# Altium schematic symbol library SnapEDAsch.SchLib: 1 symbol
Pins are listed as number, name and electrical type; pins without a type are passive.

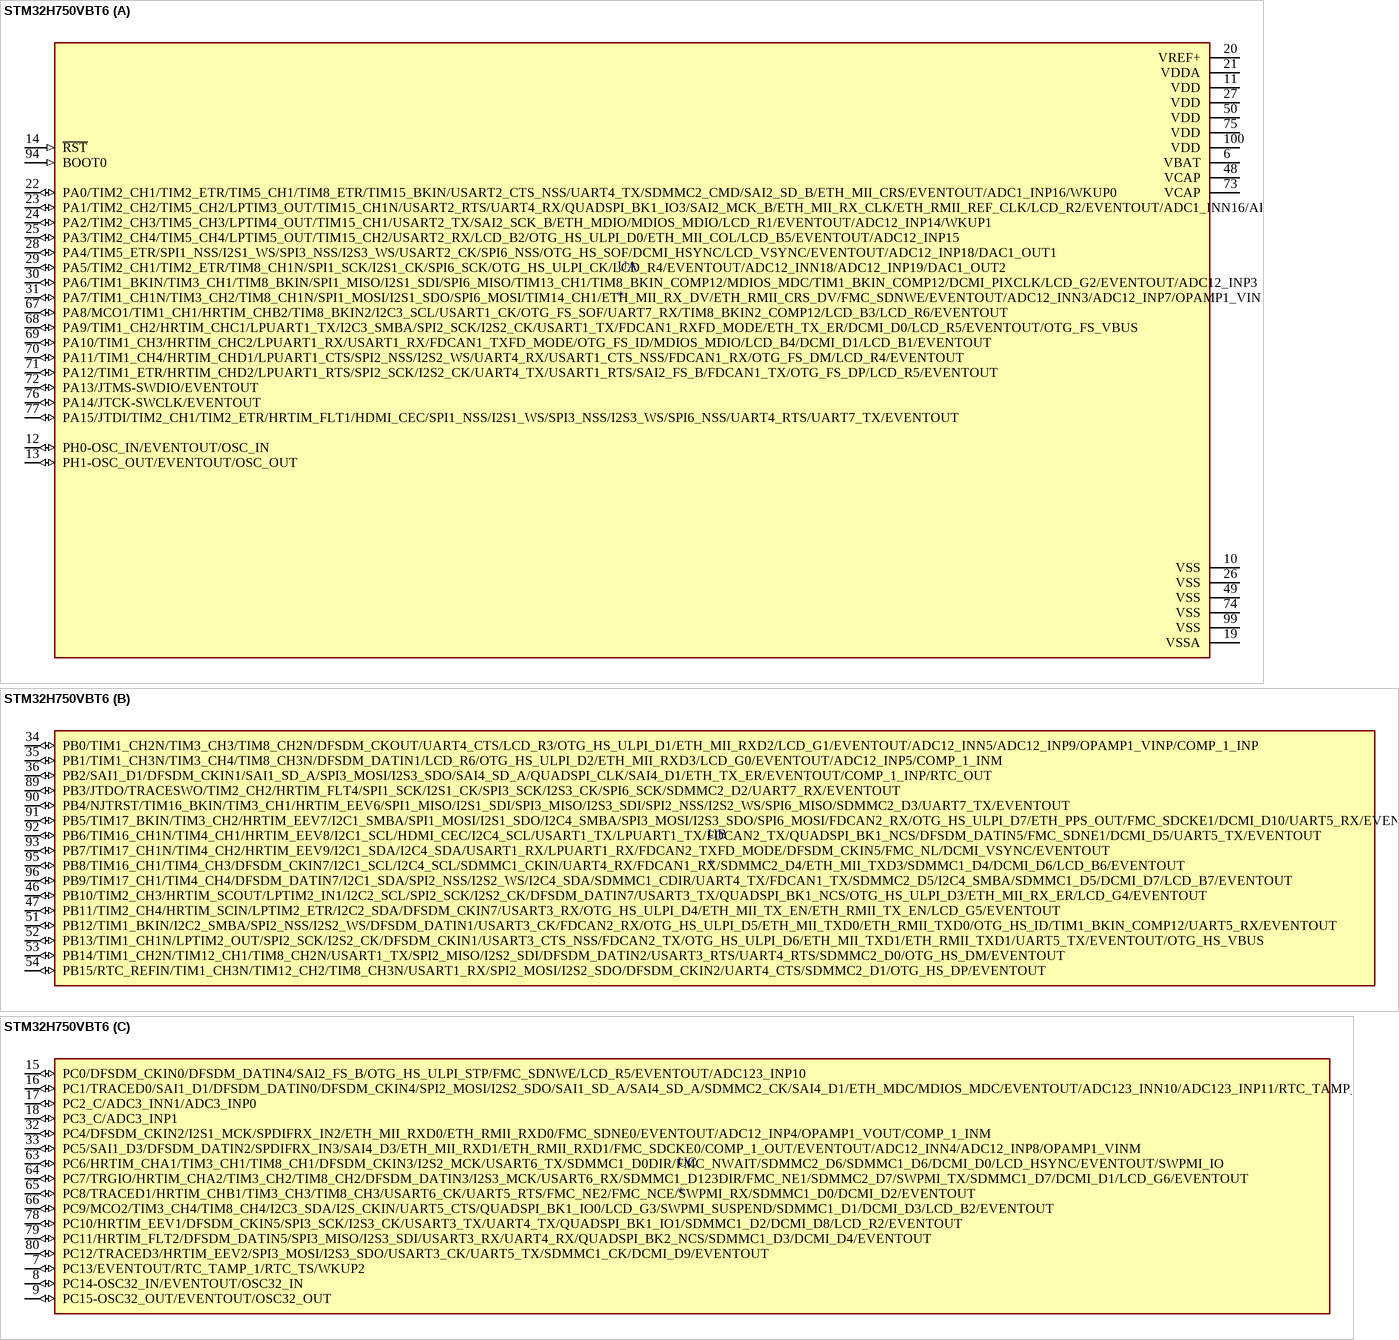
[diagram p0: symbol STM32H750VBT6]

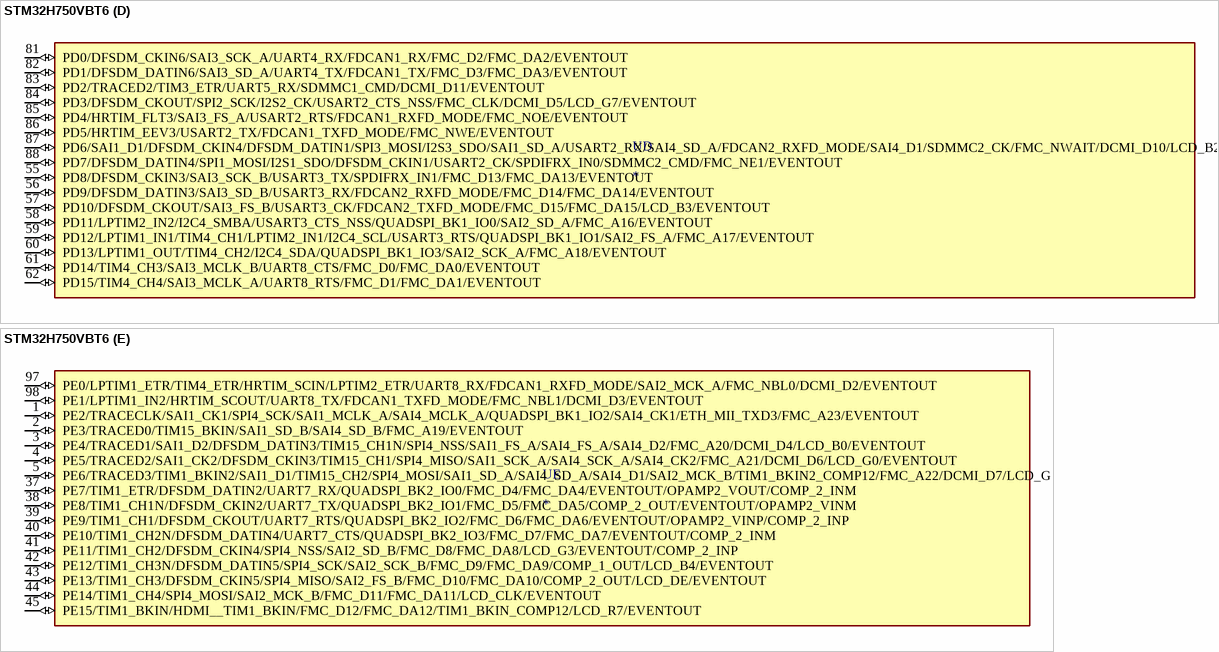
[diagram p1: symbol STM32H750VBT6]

## STM32H750VBT6
designator U
ARMÂ® CortexÂ®-M7 STM32H7 Microcontroller IC 32-Bit 480MHz 128KB _128K x 8_ FLASH 100-LQFP _14x14_; MF: STMicroelectronics; MP: STM32H750VBT6
footprint QFP50P1600X1600X160-100N
part A pins: 6 VBAT (power), 10 VSS (power), 11 VDD (power), 12 PH0-OSC_IN/EVENTOUT/OSC_IN (io), 13 PH1-OSC_OUT/EVENTOUT/OSC_OUT (io), 14 ~{RST} (in), 19 VSSA (power), 20 VREF+ (power), 21 VDDA (power), 22 PA0/TIM2_CH1/TIM2_ETR/TIM5_CH1/TIM8_ETR/TIM15_BKIN/USART2_CTS_NSS/UART4_TX/SDMMC2_CMD/SAI2_SD_B/ETH_MII_CRS/EVENTOUT/ADC1_INP16/WKUP0 (io), 23 PA1/TIM2_CH2/TIM5_CH2/LPTIM3_OUT/TIM15_CH1N/USART2_RTS/UART4_RX/QUADSPI_BK1_IO3/SAI2_MCK_B/ETH_MII_RX_CLK/ETH_RMII_REF_CLK/LCD_R2/EVENTOUT/ADC1_INN16/ADC1_INP17 (io), 24 PA2/TIM2_CH3/TIM5_CH3/LPTIM4_OUT/TIM15_CH1/USART2_TX/SAI2_SCK_B/ETH_MDIO/MDIOS_MDIO/LCD_R1/EVENTOUT/ADC12_INP14/WKUP1 (io), 25 PA3/TIM2_CH4/TIM5_CH4/LPTIM5_OUT/TIM15_CH2/USART2_RX/LCD_B2/OTG_HS_ULPI_D0/ETH_MII_COL/LCD_B5/EVENTOUT/ADC12_INP15 (io), 26 VSS (power), 27 VDD (power), 28 PA4/TIM5_ETR/SPI1_NSS/I2S1_WS/SPI3_NSS/I2S3_WS/USART2_CK/SPI6_NSS/OTG_HS_SOF/DCMI_HSYNC/LCD_VSYNC/EVENTOUT/ADC12_INP18/DAC1_OUT1 (io), 29 PA5/TIM2_CH1/TIM2_ETR/TIM8_CH1N/SPI1_SCK/I2S1_CK/SPI6_SCK/OTG_HS_ULPI_CK/LCD_R4/EVENTOUT/ADC12_INN18/ADC12_INP19/DAC1_OUT2 (io), 30 PA6/TIM1_BKIN/TIM3_CH1/TIM8_BKIN/SPI1_MISO/I2S1_SDI/SPI6_MISO/TIM13_CH1/TIM8_BKIN_COMP12/MDIOS_MDC/TIM1_BKIN_COMP12/DCMI_PIXCLK/LCD_G2/EVENTOUT/ADC12_INP3 (io), 31 PA7/TIM1_CH1N/TIM3_CH2/TIM8_CH1N/SPI1_MOSI/I2S1_SDO/SPI6_MOSI/TIM14_CH1/ETH_MII_RX_DV/ETH_RMII_CRS_DV/FMC_SDNWE/EVENTOUT/ADC12_INN3/ADC12_INP7/OPAMP1_VINM (io), 48 VCAP (power), 49 VSS (power), 50 VDD (power), 67 PA8/MCO1/TIM1_CH1/HRTIM_CHB2/TIM8_BKIN2/I2C3_SCL/USART1_CK/OTG_FS_SOF/UART7_RX/TIM8_BKIN2_COMP12/LCD_B3/LCD_R6/EVENTOUT (io), 68 PA9/TIM1_CH2/HRTIM_CHC1/LPUART1_TX/I2C3_SMBA/SPI2_SCK/I2S2_CK/USART1_TX/FDCAN1_RXFD_MODE/ETH_TX_ER/DCMI_D0/LCD_R5/EVENTOUT/OTG_FS_VBUS (io), 69 PA10/TIM1_CH3/HRTIM_CHC2/LPUART1_RX/USART1_RX/FDCAN1_TXFD_MODE/OTG_FS_ID/MDIOS_MDIO/LCD_B4/DCMI_D1/LCD_B1/EVENTOUT (io), 70 PA11/TIM1_CH4/HRTIM_CHD1/LPUART1_CTS/SPI2_NSS/I2S2_WS/UART4_RX/USART1_CTS_NSS/FDCAN1_RX/OTG_FS_DM/LCD_R4/EVENTOUT (io), 71 PA12/TIM1_ETR/HRTIM_CHD2/LPUART1_RTS/SPI2_SCK/I2S2_CK/UART4_TX/USART1_RTS/SAI2_FS_B/FDCAN1_TX/OTG_FS_DP/LCD_R5/EVENTOUT (io), 72 PA13/JTMS-SWDIO/EVENTOUT (io), 73 VCAP (power), 74 VSS (power), 75 VDD (power), 76 PA14/JTCK-SWCLK/EVENTOUT (io), 77 PA15/JTDI/TIM2_CH1/TIM2_ETR/HRTIM_FLT1/HDMI_CEC/SPI1_NSS/I2S1_WS/SPI3_NSS/I2S3_WS/SPI6_NSS/UART4_RTS/UART7_TX/EVENTOUT (io), 94 BOOT0 (in), 99 VSS (power), 100 VDD (power)
part B pins: 34 PB0/TIM1_CH2N/TIM3_CH3/TIM8_CH2N/DFSDM_CKOUT/UART4_CTS/LCD_R3/OTG_HS_ULPI_D1/ETH_MII_RXD2/LCD_G1/EVENTOUT/ADC12_INN5/ADC12_INP9/OPAMP1_VINP/COMP_1_INP (io), 35 PB1/TIM1_CH3N/TIM3_CH4/TIM8_CH3N/DFSDM_DATIN1/LCD_R6/OTG_HS_ULPI_D2/ETH_MII_RXD3/LCD_G0/EVENTOUT/ADC12_INP5/COMP_1_INM (io), 36 PB2/SAI1_D1/DFSDM_CKIN1/SAI1_SD_A/SPI3_MOSI/I2S3_SDO/SAI4_SD_A/QUADSPI_CLK/SAI4_D1/ETH_TX_ER/EVENTOUT/COMP_1_INP/RTC_OUT (io), 46 PB10/TIM2_CH3/HRTIM_SCOUT/LPTIM2_IN1/I2C2_SCL/SPI2_SCK/I2S2_CK/DFSDM_DATIN7/USART3_TX/QUADSPI_BK1_NCS/OTG_HS_ULPI_D3/ETH_MII_RX_ER/LCD_G4/EVENTOUT (io), 47 PB11/TIM2_CH4/HRTIM_SCIN/LPTIM2_ETR/I2C2_SDA/DFSDM_CKIN7/USART3_RX/OTG_HS_ULPI_D4/ETH_MII_TX_EN/ETH_RMII_TX_EN/LCD_G5/EVENTOUT (io), 51 PB12/TIM1_BKIN/I2C2_SMBA/SPI2_NSS/I2S2_WS/DFSDM_DATIN1/USART3_CK/FDCAN2_RX/OTG_HS_ULPI_D5/ETH_MII_TXD0/ETH_RMII_TXD0/OTG_HS_ID/TIM1_BKIN_COMP12/UART5_RX/EVENTOUT (io), 52 PB13/TIM1_CH1N/LPTIM2_OUT/SPI2_SCK/I2S2_CK/DFSDM_CKIN1/USART3_CTS_NSS/FDCAN2_TX/OTG_HS_ULPI_D6/ETH_MII_TXD1/ETH_RMII_TXD1/UART5_TX/EVENTOUT/OTG_HS_VBUS (io), 53 PB14/TIM1_CH2N/TIM12_CH1/TIM8_CH2N/USART1_TX/SPI2_MISO/I2S2_SDI/DFSDM_DATIN2/USART3_RTS/UART4_RTS/SDMMC2_D0/OTG_HS_DM/EVENTOUT (io), 54 PB15/RTC_REFIN/TIM1_CH3N/TIM12_CH2/TIM8_CH3N/USART1_RX/SPI2_MOSI/I2S2_SDO/DFSDM_CKIN2/UART4_CTS/SDMMC2_D1/OTG_HS_DP/EVENTOUT (io), 89 PB3/JTDO/TRACESWO/TIM2_CH2/HRTIM_FLT4/SPI1_SCK/I2S1_CK/SPI3_SCK/I2S3_CK/SPI6_SCK/SDMMC2_D2/UART7_RX/EVENTOUT (io), 90 PB4/NJTRST/TIM16_BKIN/TIM3_CH1/HRTIM_EEV6/SPI1_MISO/I2S1_SDI/SPI3_MISO/I2S3_SDI/SPI2_NSS/I2S2_WS/SPI6_MISO/SDMMC2_D3/UART7_TX/EVENTOUT (io), 91 PB5/TIM17_BKIN/TIM3_CH2/HRTIM_EEV7/I2C1_SMBA/SPI1_MOSI/I2S1_SDO/I2C4_SMBA/SPI3_MOSI/I2S3_SDO/SPI6_MOSI/FDCAN2_RX/OTG_HS_ULPI_D7/ETH_PPS_OUT/FMC_SDCKE1/DCMI_D10/UART5_RX/EVENTOUT (io), 92 PB6/TIM16_CH1N/TIM4_CH1/HRTIM_EEV8/I2C1_SCL/HDMI_CEC/I2C4_SCL/USART1_TX/LPUART1_TX/FDCAN2_TX/QUADSPI_BK1_NCS/DFSDM_DATIN5/FMC_SDNE1/DCMI_D5/UART5_TX/EVENTOUT (io), 93 PB7/TIM17_CH1N/TIM4_CH2/HRTIM_EEV9/I2C1_SDA/I2C4_SDA/USART1_RX/LPUART1_RX/FDCAN2_TXFD_MODE/DFSDM_CKIN5/FMC_NL/DCMI_VSYNC/EVENTOUT (io), 95 PB8/TIM16_CH1/TIM4_CH3/DFSDM_CKIN7/I2C1_SCL/I2C4_SCL/SDMMC1_CKIN/UART4_RX/FDCAN1_RX/SDMMC2_D4/ETH_MII_TXD3/SDMMC1_D4/DCMI_D6/LCD_B6/EVENTOUT (io), 96 PB9/TIM17_CH1/TIM4_CH4/DFSDM_DATIN7/I2C1_SDA/SPI2_NSS/I2S2_WS/I2C4_SDA/SDMMC1_CDIR/UART4_TX/FDCAN1_TX/SDMMC2_D5/I2C4_SMBA/SDMMC1_D5/DCMI_D7/LCD_B7/EVENTOUT (io)
part C pins: 7 PC13/EVENTOUT/RTC_TAMP_1/RTC_TS/WKUP2 (io), 8 PC14-OSC32_IN/EVENTOUT/OSC32_IN (io), 9 PC15-OSC32_OUT/EVENTOUT/OSC32_OUT (io), 15 PC0/DFSDM_CKIN0/DFSDM_DATIN4/SAI2_FS_B/OTG_HS_ULPI_STP/FMC_SDNWE/LCD_R5/EVENTOUT/ADC123_INP10 (io), 16 PC1/TRACED0/SAI1_D1/DFSDM_DATIN0/DFSDM_CKIN4/SPI2_MOSI/I2S2_SDO/SAI1_SD_A/SAI4_SD_A/SDMMC2_CK/SAI4_D1/ETH_MDC/MDIOS_MDC/EVENTOUT/ADC123_INN10/ADC123_INP11/RTC_TAMP_3/WKUP5 (io), 17 PC2_C/ADC3_INN1/ADC3_INP0 (io), 18 PC3_C/ADC3_INP1 (io), 32 PC4/DFSDM_CKIN2/I2S1_MCK/SPDIFRX_IN2/ETH_MII_RXD0/ETH_RMII_RXD0/FMC_SDNE0/EVENTOUT/ADC12_INP4/OPAMP1_VOUT/COMP_1_INM (io), 33 PC5/SAI1_D3/DFSDM_DATIN2/SPDIFRX_IN3/SAI4_D3/ETH_MII_RXD1/ETH_RMII_RXD1/FMC_SDCKE0/COMP_1_OUT/EVENTOUT/ADC12_INN4/ADC12_INP8/OPAMP1_VINM (io), 63 PC6/HRTIM_CHA1/TIM3_CH1/TIM8_CH1/DFSDM_CKIN3/I2S2_MCK/USART6_TX/SDMMC1_D0DIR/FMC_NWAIT/SDMMC2_D6/SDMMC1_D6/DCMI_D0/LCD_HSYNC/EVENTOUT/SWPMI_IO (io), 64 PC7/TRGIO/HRTIM_CHA2/TIM3_CH2/TIM8_CH2/DFSDM_DATIN3/I2S3_MCK/USART6_RX/SDMMC1_D123DIR/FMC_NE1/SDMMC2_D7/SWPMI_TX/SDMMC1_D7/DCMI_D1/LCD_G6/EVENTOUT (io), 65 PC8/TRACED1/HRTIM_CHB1/TIM3_CH3/TIM8_CH3/USART6_CK/UART5_RTS/FMC_NE2/FMC_NCE/SWPMI_RX/SDMMC1_D0/DCMI_D2/EVENTOUT (io), 66 PC9/MCO2/TIM3_CH4/TIM8_CH4/I2C3_SDA/I2S_CKIN/UART5_CTS/QUADSPI_BK1_IO0/LCD_G3/SWPMI_SUSPEND/SDMMC1_D1/DCMI_D3/LCD_B2/EVENTOUT (io), 78 PC10/HRTIM_EEV1/DFSDM_CKIN5/SPI3_SCK/I2S3_CK/USART3_TX/UART4_TX/QUADSPI_BK1_IO1/SDMMC1_D2/DCMI_D8/LCD_R2/EVENTOUT (io), 79 PC11/HRTIM_FLT2/DFSDM_DATIN5/SPI3_MISO/I2S3_SDI/USART3_RX/UART4_RX/QUADSPI_BK2_NCS/SDMMC1_D3/DCMI_D4/EVENTOUT (io), 80 PC12/TRACED3/HRTIM_EEV2/SPI3_MOSI/I2S3_SDO/USART3_CK/UART5_TX/SDMMC1_CK/DCMI_D9/EVENTOUT (io)
part D pins: 55 PD8/DFSDM_CKIN3/SAI3_SCK_B/USART3_TX/SPDIFRX_IN1/FMC_D13/FMC_DA13/EVENTOUT (io), 56 PD9/DFSDM_DATIN3/SAI3_SD_B/USART3_RX/FDCAN2_RXFD_MODE/FMC_D14/FMC_DA14/EVENTOUT (io), 57 PD10/DFSDM_CKOUT/SAI3_FS_B/USART3_CK/FDCAN2_TXFD_MODE/FMC_D15/FMC_DA15/LCD_B3/EVENTOUT (io), 58 PD11/LPTIM2_IN2/I2C4_SMBA/USART3_CTS_NSS/QUADSPI_BK1_IO0/SAI2_SD_A/FMC_A16/EVENTOUT (io), 59 PD12/LPTIM1_IN1/TIM4_CH1/LPTIM2_IN1/I2C4_SCL/USART3_RTS/QUADSPI_BK1_IO1/SAI2_FS_A/FMC_A17/EVENTOUT (io), 60 PD13/LPTIM1_OUT/TIM4_CH2/I2C4_SDA/QUADSPI_BK1_IO3/SAI2_SCK_A/FMC_A18/EVENTOUT (io), 61 PD14/TIM4_CH3/SAI3_MCLK_B/UART8_CTS/FMC_D0/FMC_DA0/EVENTOUT (io), 62 PD15/TIM4_CH4/SAI3_MCLK_A/UART8_RTS/FMC_D1/FMC_DA1/EVENTOUT (io), 81 PD0/DFSDM_CKIN6/SAI3_SCK_A/UART4_RX/FDCAN1_RX/FMC_D2/FMC_DA2/EVENTOUT (io), 82 PD1/DFSDM_DATIN6/SAI3_SD_A/UART4_TX/FDCAN1_TX/FMC_D3/FMC_DA3/EVENTOUT (io), 83 PD2/TRACED2/TIM3_ETR/UART5_RX/SDMMC1_CMD/DCMI_D11/EVENTOUT (io), 84 PD3/DFSDM_CKOUT/SPI2_SCK/I2S2_CK/USART2_CTS_NSS/FMC_CLK/DCMI_D5/LCD_G7/EVENTOUT (io), 85 PD4/HRTIM_FLT3/SAI3_FS_A/USART2_RTS/FDCAN1_RXFD_MODE/FMC_NOE/EVENTOUT (io), 86 PD5/HRTIM_EEV3/USART2_TX/FDCAN1_TXFD_MODE/FMC_NWE/EVENTOUT (io), 87 PD6/SAI1_D1/DFSDM_CKIN4/DFSDM_DATIN1/SPI3_MOSI/I2S3_SDO/SAI1_SD_A/USART2_RX/SAI4_SD_A/FDCAN2_RXFD_MODE/SAI4_D1/SDMMC2_CK/FMC_NWAIT/DCMI_D10/LCD_B2/EVENTOUT (io), 88 PD7/DFSDM_DATIN4/SPI1_MOSI/I2S1_SDO/DFSDM_CKIN1/USART2_CK/SPDIFRX_IN0/SDMMC2_CMD/FMC_NE1/EVENTOUT (io)
part E pins: 1 PE2/TRACECLK/SAI1_CK1/SPI4_SCK/SAI1_MCLK_A/SAI4_MCLK_A/QUADSPI_BK1_IO2/SAI4_CK1/ETH_MII_TXD3/FMC_A23/EVENTOUT (io), 2 PE3/TRACED0/TIM15_BKIN/SAI1_SD_B/SAI4_SD_B/FMC_A19/EVENTOUT (io), 3 PE4/TRACED1/SAI1_D2/DFSDM_DATIN3/TIM15_CH1N/SPI4_NSS/SAI1_FS_A/SAI4_FS_A/SAI4_D2/FMC_A20/DCMI_D4/LCD_B0/EVENTOUT (io), 4 PE5/TRACED2/SAI1_CK2/DFSDM_CKIN3/TIM15_CH1/SPI4_MISO/SAI1_SCK_A/SAI4_SCK_A/SAI4_CK2/FMC_A21/DCMI_D6/LCD_G0/EVENTOUT (io), 5 PE6/TRACED3/TIM1_BKIN2/SAI1_D1/TIM15_CH2/SPI4_MOSI/SAI1_SD_A/SAI4_SD_A/SAI4_D1/SAI2_MCK_B/TIM1_BKIN2_COMP12/FMC_A22/DCMI_D7/LCD_G1/EVENTOUT (io), 37 PE7/TIM1_ETR/DFSDM_DATIN2/UART7_RX/QUADSPI_BK2_IO0/FMC_D4/FMC_DA4/EVENTOUT/OPAMP2_VOUT/COMP_2_INM (io), 38 PE8/TIM1_CH1N/DFSDM_CKIN2/UART7_TX/QUADSPI_BK2_IO1/FMC_D5/FMC_DA5/COMP_2_OUT/EVENTOUT/OPAMP2_VINM (io), 39 PE9/TIM1_CH1/DFSDM_CKOUT/UART7_RTS/QUADSPI_BK2_IO2/FMC_D6/FMC_DA6/EVENTOUT/OPAMP2_VINP/COMP_2_INP (io), 40 PE10/TIM1_CH2N/DFSDM_DATIN4/UART7_CTS/QUADSPI_BK2_IO3/FMC_D7/FMC_DA7/EVENTOUT/COMP_2_INM (io), 41 PE11/TIM1_CH2/DFSDM_CKIN4/SPI4_NSS/SAI2_SD_B/FMC_D8/FMC_DA8/LCD_G3/EVENTOUT/COMP_2_INP (io), 42 PE12/TIM1_CH3N/DFSDM_DATIN5/SPI4_SCK/SAI2_SCK_B/FMC_D9/FMC_DA9/COMP_1_OUT/LCD_B4/EVENTOUT (io), 43 PE13/TIM1_CH3/DFSDM_CKIN5/SPI4_MISO/SAI2_FS_B/FMC_D10/FMC_DA10/COMP_2_OUT/LCD_DE/EVENTOUT (io), 44 PE14/TIM1_CH4/SPI4_MOSI/SAI2_MCK_B/FMC_D11/FMC_DA11/LCD_CLK/EVENTOUT (io), 45 PE15/TIM1_BKIN/HDMI__TIM1_BKIN/FMC_D12/FMC_DA12/TIM1_BKIN_COMP12/LCD_R7/EVENTOUT (io), 97 PE0/LPTIM1_ETR/TIM4_ETR/HRTIM_SCIN/LPTIM2_ETR/UART8_RX/FDCAN1_RXFD_MODE/SAI2_MCK_A/FMC_NBL0/DCMI_D2/EVENTOUT (io), 98 PE1/LPTIM1_IN2/HRTIM_SCOUT/UART8_TX/FDCAN1_TXFD_MODE/FMC_NBL1/DCMI_D3/EVENTOUT (io)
